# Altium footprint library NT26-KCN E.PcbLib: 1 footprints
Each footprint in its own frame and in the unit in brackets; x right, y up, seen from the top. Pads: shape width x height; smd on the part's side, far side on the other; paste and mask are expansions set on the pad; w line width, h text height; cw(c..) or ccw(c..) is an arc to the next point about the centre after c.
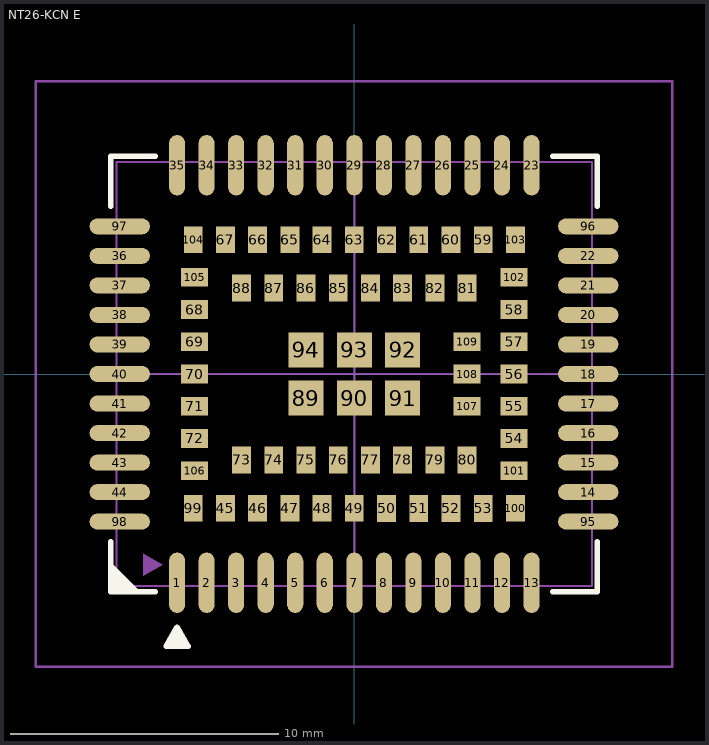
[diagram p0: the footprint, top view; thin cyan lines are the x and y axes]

## NT26-KCN E [mm]
pads (109):
  oval 0.6x2.25 smd mask+0.102: 1(-6.6,-7.775) 2(-5.5,-7.775) 3(-4.4,-7.775) 4(-3.3,-7.775) 5(-2.2,-7.775) 6(-1.1,-7.775) 7(0,-7.775) 8(1.1,-7.775) 9(2.2,-7.775) 10(3.3,-7.775) 11(4.4,-7.775) 12(5.5,-7.775) 13(6.6,-7.775) 23(6.6,7.775) 24(5.5,7.775) 25(4.4,7.775) 26(3.3,7.775) 27(2.2,7.775) 28(1.1,7.775) 29(0,7.775) 30(-1.1,7.775) 31(-2.2,7.775) 32(-3.3,7.775) 33(-4.4,7.775) 34(-5.5,7.775) 35(-6.6,7.775)
  oval 2.25x0.6 smd mask+0.102: 14(8.714,-4.4) 15(8.714,-3.3) 16(8.714,-2.2) 17(8.714,-1.1) 18(8.714,0) 19(8.714,1.1) 20(8.714,2.2) 21(8.714,3.3) 22(8.714,4.4) 36(-8.736,4.4) 37(-8.736,3.3) 38(-8.736,2.2) 39(-8.736,1.1) 40(-8.736,0) 41(-8.736,-1.1) 42(-8.736,-2.2) 43(-8.736,-3.3) 44(-8.736,-4.4) 95(8.714,-5.5) 96(8.714,5.5) 97(-8.736,5.5) 98(-8.736,-5.5)
  rect 0.7x1 smd: 45(-4.8,-5) 46(-3.6,-5) 47(-2.4,-5) 48(-1.2,-5) 49(0,-5) 50(1.2,-5.003) 51(2.4,-5.003) 52(3.6,-5.003) 53(4.8,-5.003) 59(4.8,5) 60(3.6,5) 61(2.4,5) 62(1.2,5) 63(0,5) 64(-1.2,5) 65(-2.4,5) 66(-3.6,5) 67(-4.8,5) 73(-4.2,-3.2) 74(-3,-3.2) 75(-1.8,-3.2) 76(-0.6,-3.2) 77(0.6,-3.2) 78(1.8,-3.2) 79(3,-3.2) 80(4.2,-3.2) 81(4.2,3.2) 82(3,3.2) 83(1.8,3.2) 84(0.6,3.2) 85(-0.6,3.2) 86(-1.8,3.2) 87(-3,3.2) 88(-4.2,3.2) 99(-6,-5) 100(6,-5) 103(6,5) 104(-6,5)
  rect 1x0.7 smd: 54(5.95,-2.4) 55(5.95,-1.2) 56(5.95,0) 57(5.95,1.2) 58(5.95,2.4) 68(-5.95,2.4) 69(-5.95,1.2) 70(-5.95,0) 71(-5.95,-1.2) 72(-5.95,-2.4) 101(5.95,-3.6) 102(5.95,3.6) 105(-5.95,3.6) 106(-5.95,-3.6) 107(4.2,-1.2) 108(4.2,0) 109(4.2,1.2)
  rect 1.3x1.3 smd: 89(-1.8,-0.9) 90(0,-0.9) 91(1.8,-0.9) 92(1.8,0.9) 93(0,0.9) 94(-1.8,0.9)
Top Layer:
  lines w0.076: 0,7.775 0,7.775
Top Overlay:
  region: -6.187,-10.144 -6.601,-9.42 -7.013,-10.144
  region: -9.068,-8.108 -7.984,-8.097 -9.059,-7.023
  lines w0.199: -9.068,-6.25 -9.068,-8.108 -7.417,-8.108 ; -9.068,6.25 -9.068,8.108 -7.417,8.108 ; 7.395,-8.108 9.046,-8.108 9.046,-6.25 ; 7.395,8.108 9.046,8.108 9.046,6.25 ; -7.013,-10.144 -6.187,-10.144 -6.601,-9.42 -7.013,-10.144
Mechanical 1:
  region: -7.857,-7.514 -7.133,-7.1 -7.857,-6.688
  lines w0.076: -8.85,0 8.85,0 ; 0,-7.9 0,7.9 ; -8.85,-7.9 8.85,-7.9 8.85,7.9 -8.85,7.9 -8.85,-7.9
  lines w0.09: -11.861,10.9 11.839,10.9 ; -11.861,10.9 11.839,10.9 ; -11.861,10.9 -11.861,-10.9 11.839,-10.9 11.839,10.9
